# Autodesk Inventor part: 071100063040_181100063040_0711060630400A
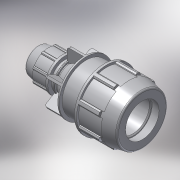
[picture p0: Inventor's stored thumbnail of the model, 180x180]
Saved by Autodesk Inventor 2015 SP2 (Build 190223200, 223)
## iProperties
Created: 2017-02
Part Number: 071100063040_181100063040_0711060630400A
Material: PVC-Piping
Description: PLASSON REDUCING COUPLER 63-40
Document SubType Name: Modeling
Designer: KIM
Mass: 92.6774 g
Surface Area: 199.44 cm^2
Volume: 66.1981 cm^3
Density: 1.4 g/cm^3
Appearance: Smooth - White
Author: KIM
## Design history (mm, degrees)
derived "07110.ipt"
feature "Solid1::07110.ipt"
tag "TaggingFeature1"
body "Solid1"
other parameters: "d2" = 63, "d4" = 17.33333, "d5" = 29.71429, "d7" = 113, "d9" = 29.71429, "d11" = 2.97143, "d12" = 90.4, "d13" = 120 deg, "d14" = 94.5, "d15" = 12 deg, "d16" = 101.7, "d18" = 3.15, "d19" = 35 deg, "d20" = 17.5 deg, "d21" = 105.09, "d23" = 0, "d25" = 360 deg, "d27" = 2.26, "d42" = 45.76, "d46" = 1.89, "d51" = 208, "d52" = 29.71429, "d53" = 12 deg, "d58" = 56.7, "d59" = 36, "d60" = 73.8, "d61" = 65.6, "d62" = 20.8, "d63" = 33.28, "d64" = 120 deg, "d65" = 82, "d68" = 14.85714, "d74" = 76.26, "d75" = 35 deg, "d76" = 17.5 deg, "d78" = 0, "d80" = 360 deg, "d85" = 1.64, "d88" = 0.8, "d93" = 82, "d94" = 79.1, "d97" = 3.06667, "d98" = 5.46667, "d99" = 0, "d100" = 4.52, "d102" = 360 deg, "d104" = 2, "d106" = 0, "d107" = 5.46667, "d108" = 0, "d109" = 5.46667, "d110" = 0, "d_" = 63, "E_" = 113, "H_" = 208, "E_1" = 82, "l_1" = 82, "d96" = 9.2
